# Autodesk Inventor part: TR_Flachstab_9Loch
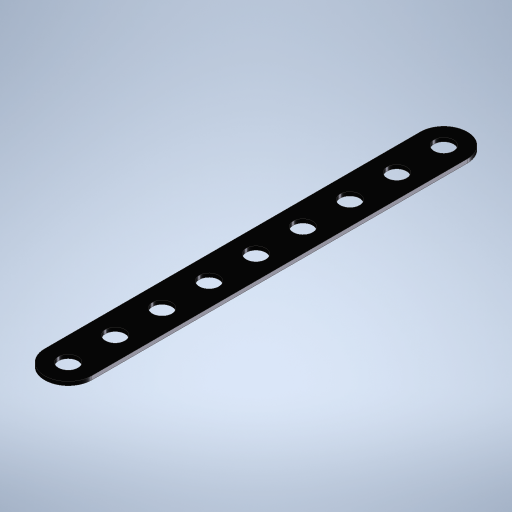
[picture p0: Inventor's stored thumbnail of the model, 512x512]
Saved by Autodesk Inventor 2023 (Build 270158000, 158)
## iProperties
Created: 2023-11
Part Number: TR_Flachstab_9Loch
Material: Edelstahl
Document SubType Name: Modeling
Designer: Admin
Density: 8 g/cm^3
Appearance: Halbpoliert
Author: Admin
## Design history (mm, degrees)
sketch "Skizze1"
  geometry: L1 (0, 40)-(0, -40); L2 (-5, 40)-(-5, -40); L3 (5, -40)-(5, 40); A1 r 5 centre (0, 40) between (5, 40) and (-5, 40); A2 r 5 centre (0, -40) between (-5, -40) and (5, -40); 3 further points
  constraints: 8 end point, 4 point on circle, 4 tangent, 2 centre point, 2 midpoint, 1 horizontal alignment, 1 parallel, 1 vertical, 1 vertical alignment
  dimensions: "d0" = 80 distance of L1.start L1.end (computed from Loch, Einheitsmaß); "d1" = 5 radius of A1 (= 0.5 x Einheitsmaß)
extrude "Extrusion1" new body sketch "Skizze1" distance "d5" = 0.8 (= Dicke); taper "d6" = 0 deg
sketch "Skizze2"
  geometry: C1 r 2.075 at (0, 40); A1 r 5 centre (0, 40) between (5, 40) and (-5, 40) reference; 1 further point
  constraints: 1 centre point, 1 coincident
  dimensions: "d7" = 4.15 diameter of C1 (= 2 x Radius)
extrude "Extrusion2" cut sketch "Skizze2" stored distance "d8" = 10; taper "d9" = 0 deg
pattern_linear "Rechteckige Anordnung1" dims "d12" = 10 (= Einheitsmaß)
node "Volumenkörper1"
other parameters: "Einheitsmaß" = 10 [user parameter; used in 3 equation terms], "Radius" = 2.075 [user parameter; used in 1 equation term], "Fasen" = 0.5 [user parameter], "Dicke" = 0.8 [user parameter; used in 1 equation term]
